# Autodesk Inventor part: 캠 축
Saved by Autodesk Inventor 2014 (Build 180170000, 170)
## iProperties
Created: 2026-06
Part Number: 캠 축
Material: 강철, 탄소
Document SubType Name: Modeling
Designer: dg
Density: 7.87 g/cm^3
Appearance: 반연마
Mass: 268.772 g
Surface Area: 81.6995 cm^2
Volume: 34.1514 cm^3
Author: jhkim
Creation Date: 2026-05-29
Sending System: Autodesk Inventor 2027
Preprocessor: ST-DEVELOPER v20.1
Author: dg
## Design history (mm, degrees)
node "캠 축1"
node "솔리드1"
node "기준1"
